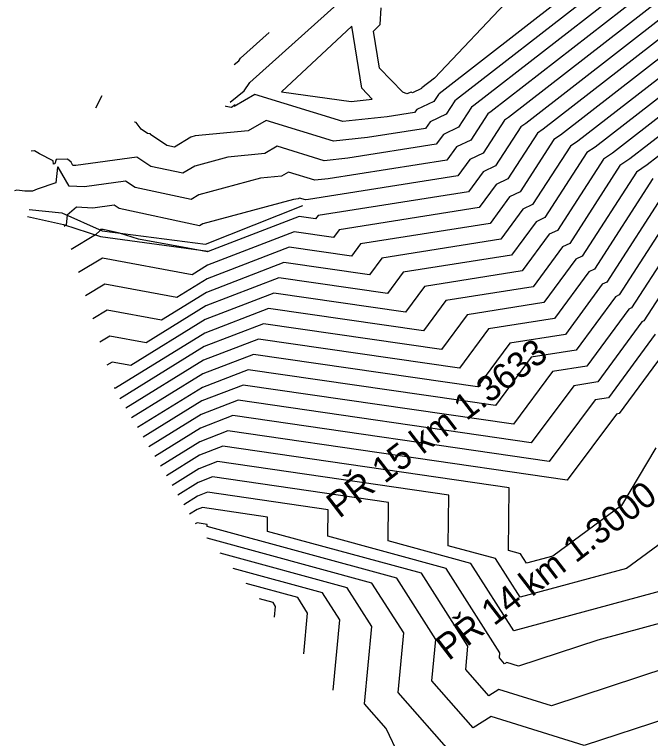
# Model space of a CAD drawing. Extents: x -549238 to -546764, y -1036895 to -1033794.
# Drawn here: x -549025.3 to -548800.9, y -1034580.6 to -1034325.1 of the extents above; entities that cross this region are included whole.
import ezdxf

# ---------------------------------------------------------------- set-up
doc = ezdxf.new("R2010")
doc.units = 0
for name, color, linetype in [('hlavni_vrst', 7, 'Continuous'), ('hrana_L', 7, 'Continuous'), ('norm_vrst', 7, 'Continuous'), ('x_popis_pricne_rezy_C12', 7, 'Continuous')]:
    doc.layers.add(name, color=color, linetype=linetype)

msp = doc.modelspace()

# ---------------------------------------------------------------- linework, layer by layer
at = {"layer": 'hlavni_vrst'}
for p, q in [((-548827.23, -1034315.61), (-548875.4, -1034353.08)), ((-548942.26, -1034349.1), (-548911.49, -1034321.45)), ((-548791.42, -1034322), (-548844.83, -1034363.54)), ((-548906.26, -1034329.26), (-548931.06, -1034352.35)), ((-548902.78, -1034351.17), (-548906.26, -1034329.26)), ((-548780.95, -1034348.1), (-548814.25, -1034374.01)), ((-548944.23, -1034352.06), (-548942.26, -1034349.1)), ((-548899.05, -1034354.99), (-548902.78, -1034351.17)), ((-548949.17, -1034356.03), (-548944.23, -1034352.06)), ((-548940.52, -1034353.34), (-548947.76, -1034357.55)), ((-548909.51, -1034362.87), (-548940.52, -1034353.34)), ((-548931.06, -1034352.35), (-548906.47, -1034355.85)), ((-548875.73, -1034353.29), (-548877.34, -1034355.79)), ((-548875.4, -1034353.08), (-548875.73, -1034353.29)), ((-548906.47, -1034355.85), (-548899.05, -1034354.99)), ((-548877.34, -1034355.79), (-548883.32, -1034358.63)), ((-548950.73, -1034357.6), (-548950.77, -1034357.3)), ((-548948.77, -1034357.93), (-548950.73, -1034357.6)), ((-548947.43, -1034357.02), (-548948.77, -1034357.93)), ((-548947.76, -1034357.55), (-548947.43, -1034357.02)), ((-548883.32, -1034358.63), (-548884.11, -1034359.7)), ((-548893.78, -1034361.24), (-548909.51, -1034362.87)), ((-548884.11, -1034359.7), (-548893.78, -1034361.24)), ((-548844.83, -1034363.54), (-548846.62, -1034364.71)), ((-548846.62, -1034364.71), (-548855.54, -1034378.56)), ((-548814.25, -1034374.01), (-548817.51, -1034376.13)), ((-548817.51, -1034376.13), (-548833.75, -1034401.33)), ((-548855.54, -1034378.56), (-548859.96, -1034380.65)), ((-548859.96, -1034380.65), (-548865.11, -1034387.66)), ((-548865.11, -1034387.66), (-548918.22, -1034396.08)), ((-548788.4, -1034387.55), (-548811.96, -1034424.09)), ((-548924.84, -1034396.37), (-548956.96, -1034408.78)), ((-548919.06, -1034397.21), (-548924.84, -1034396.37)), ((-548918.22, -1034396.08), (-548919.06, -1034397.21)), ((-548995.14, -1034401.33), (-548996.72, -1034402.87)), ((-548995.12, -1034401.14), (-548995.14, -1034401.33)), ((-548994.93, -1034400.98), (-548995.12, -1034401.14)), ((-548994.6, -1034401), (-548994.93, -1034400.98)), ((-548994.18, -1034400.94), (-548994.6, -1034401)), ((-548994.08, -1034401.01), (-548994.18, -1034400.94)), ((-548988.34, -1034402.23), (-548994.08, -1034401.01)), ((-548981.56, -1034404.41), (-548988.34, -1034402.23)), ((-548833.75, -1034401.33), (-548836.59, -1034402.68)), ((-548996.72, -1034402.87), (-549005.29, -1034408.04)), ((-548964.19, -1034407.61), (-548981.56, -1034404.41)), ((-548836.59, -1034402.68), (-548846.11, -1034415.62)), ((-548957.17, -1034408.91), (-548964.19, -1034407.61)), ((-548956.96, -1034408.78), (-548957.17, -1034408.91)), ((-548846.11, -1034415.62), (-548880.61, -1034421.09)), ((-548880.61, -1034421.09), (-548887.34, -1034430.14)), ((-548933.84, -1034423.41), (-548958, -1034432.75)), ((-548887.34, -1034430.14), (-548933.84, -1034423.41)), ((-548813.23, -1034424.7), (-548827.11, -1034443.57)), ((-548811.96, -1034424.09), (-548813.23, -1034424.7)), ((-548958, -1034432.75), (-548984.28, -1034449)), ((-548827.11, -1034443.57), (-548843, -1034446.09)), ((-548990.91, -1034447.77), (-548992.7, -1034448.85)), ((-548984.28, -1034449), (-548990.91, -1034447.77)), ((-548843, -1034446.09), (-548855.62, -1034463.08)), ((-548942.84, -1034450.45), (-548959.04, -1034456.71)), ((-548855.62, -1034463.08), (-548942.84, -1034450.45)), ((-548959.04, -1034456.71), (-548981.97, -1034470.89)), ((-548951.84, -1034477.49), (-548960.08, -1034480.67)), ((-548850.73, -1034492.13), (-548951.84, -1034477.49)), ((-548798.95, -1034478.01), (-548811.07, -1034498.41)), ((-548960.08, -1034480.67), (-548971.75, -1034487.89)), ((-548850.95, -1034514.29), (-548850.73, -1034492.13)), ((-548811.07, -1034498.41), (-548835.34, -1034516.27)), ((-548961.12, -1034504.64), (-548961.53, -1034504.89)), ((-548960.84, -1034504.53), (-548961.12, -1034504.64)), ((-548957.32, -1034505.04), (-548960.84, -1034504.53)), ((-548957.33, -1034505.81), (-548957.32, -1034505.04)), ((-548890.45, -1034524.01), (-548957.33, -1034505.81)), ((-548846.81, -1034515.42), (-548850.95, -1034514.29)), ((-548844.67, -1034518.77), (-548846.81, -1034515.42)), ((-548835.34, -1034516.27), (-548844.67, -1034518.77)), ((-548876.65, -1034545.68), (-548890.45, -1034524.01)), ((-548934.1, -1034532.6), (-548938.9, -1034531.29)), ((-548938.9, -1034531.29), (-548938.9, -1034531.29)), ((-548933.17, -1034534.06), (-548934.1, -1034532.6)), ((-548933.52, -1034537.84), (-548933.17, -1034534.06)), ((-548877.99, -1034560.29), (-548876.65, -1034545.68)), ((-548863.43, -1034576.88), (-548877.99, -1034560.29)), ((-548752.79, -1034559.55), (-548824.26, -1034583.07)), ((-548857.14, -1034572.85), (-548863.43, -1034576.88)), ((-548824.26, -1034583.07), (-548857.14, -1034572.85))]:
    msp.add_line(p, q, dxfattribs=at)
at = {"layer": 'hrana_L'}
for p, q in [((-549020.11, -1034393.96), (-549008.6, -1034395.1)), ((-548957.94, -1034406.11), (-548923.56, -1034392.53)), ((-549020.77, -1034396.39), (-549008.01, -1034399.22)), ((-549008.6, -1034395.1), (-548994.42, -1034401.45)), ((-549008.01, -1034399.22), (-548994.94, -1034403.44)), ((-548994.42, -1034401.45), (-548957.94, -1034406.11)), ((-548994.94, -1034403.44), (-548956.95, -1034408.59))]:
    msp.add_line(p, q, dxfattribs=at)
at = {"layer": 'norm_vrst'}
for p, q in [((-548832.35, -1034300.26), (-548877.14, -1034347.58)), ((-548799.8, -1034301.11), (-548869.29, -1034355.17)), ((-548797.7, -1034306.33), (-548863.17, -1034357.27)), ((-548795.61, -1034311.56), (-548857.06, -1034359.36)), ((-548793.52, -1034316.78), (-548850.94, -1034361.45)), ((-548896.31, -1034328.69), (-548895.92, -1034322.78)), ((-548789.33, -1034327.22), (-548838.71, -1034365.64)), ((-548898.6, -1034331.03), (-548896.31, -1034328.69)), ((-548945.53, -1034340.53), (-548935.41, -1034331.44)), ((-548896.52, -1034344.11), (-548898.6, -1034331.03)), ((-548787.23, -1034332.44), (-548832.6, -1034367.73)), ((-548785.14, -1034337.66), (-548826.48, -1034369.82)), ((-548946.18, -1034341.51), (-548945.53, -1034340.53)), ((-548947.8, -1034342.82), (-548946.18, -1034341.51)), ((-548783.05, -1034342.88), (-548820.37, -1034371.91)), ((-548888.3, -1034352.54), (-548896.52, -1034344.11)), ((-548877.14, -1034347.58), (-548881.52, -1034350.99)), ((-548881.55, -1034351.01), (-548881.69, -1034351.24)), ((-548881.52, -1034350.99), (-548881.55, -1034351.01)), ((-548996.66, -1034358.1), (-548994.4, -1034353.67)), ((-548886.88, -1034353.16), (-548888.3, -1034352.54)), ((-548885.35, -1034352.57), (-548886.88, -1034353.16)), ((-548884.83, -1034352.73), (-548885.35, -1034352.57)), ((-548881.69, -1034351.24), (-548884.83, -1034352.73)), ((-548778.86, -1034353.32), (-548808.14, -1034376.1)), ((-548869.9, -1034355.58), (-548872.98, -1034360.34)), ((-548869.29, -1034355.17), (-548869.9, -1034355.58)), ((-548864.08, -1034357.86), (-548868.62, -1034364.9)), ((-548863.17, -1034357.27), (-548864.08, -1034357.86)), ((-548776.77, -1034358.54), (-548802.02, -1034378.19)), ((-548872.98, -1034360.34), (-548878.65, -1034363.04)), ((-548858.26, -1034360.14), (-548864.26, -1034369.45)), ((-548857.06, -1034359.36), (-548858.26, -1034360.14)), ((-548982.93, -1034363.12), (-548982.82, -1034362.98)), ((-548982.38, -1034363.25), (-548982.93, -1034363.12)), ((-548980.67, -1034365.6), (-548982.38, -1034363.25)), ((-548936.57, -1034362.48), (-548942.86, -1034366.13)), ((-548912.78, -1034369.79), (-548936.57, -1034362.48)), ((-548878.65, -1034363.04), (-548880.31, -1034365.29)), ((-548852.44, -1034362.43), (-548859.9, -1034374)), ((-548850.94, -1034361.45), (-548852.44, -1034362.43)), ((-548980.67, -1034365.6), (-548980.68, -1034365.62)), ((-548978.45, -1034367.12), (-548980.68, -1034365.62)), ((-548942.86, -1034366.13), (-548961.6, -1034367.99)), ((-548880.31, -1034365.29), (-548900.72, -1034368.53)), ((-548868.62, -1034364.9), (-548873.98, -1034367.44)), ((-548838.71, -1034365.64), (-548840.79, -1034366.99)), ((-548977.35, -1034367.27), (-548978.45, -1034367.12)), ((-548977.38, -1034367.51), (-548977.35, -1034367.27)), ((-548971.54, -1034371.36), (-548977.38, -1034367.51)), ((-548963.12, -1034368.4), (-548968.87, -1034371.92)), ((-548961.6, -1034367.99), (-548963.12, -1034368.4)), ((-548900.72, -1034368.53), (-548912.78, -1034369.79)), ((-548873.98, -1034367.44), (-548876.51, -1034370.89)), ((-548840.79, -1034366.99), (-548851.18, -1034383.11)), ((-548832.6, -1034367.73), (-548834.97, -1034369.28)), ((-548968.87, -1034371.92), (-548971.54, -1034371.36)), ((-548932.61, -1034371.61), (-548936.99, -1034374.16)), ((-548916.06, -1034376.7), (-548932.61, -1034371.61)), ((-548876.51, -1034370.89), (-548907.66, -1034375.82)), ((-548864.26, -1034369.45), (-548869.31, -1034371.85)), ((-548834.97, -1034369.28), (-548846.83, -1034387.66)), ((-548829.15, -1034371.56), (-548842.47, -1034392.22)), ((-548826.48, -1034369.82), (-548829.15, -1034371.56)), ((-549018.28, -1034373.28), (-549019.42, -1034373.36)), ((-549016.49, -1034374.33), (-549018.28, -1034373.28)), ((-548936.99, -1034374.16), (-548950.03, -1034375.45)), ((-548869.31, -1034371.85), (-548872.71, -1034376.48)), ((-548859.9, -1034374), (-548864.63, -1034376.25)), ((-548823.33, -1034373.85), (-548838.11, -1034396.77)), ((-548820.37, -1034371.91), (-548823.33, -1034373.85)), ((-549011.66, -1034376.73), (-549016.49, -1034374.33)), ((-549011.62, -1034377.93), (-549011.66, -1034376.73)), ((-549010.65, -1034376.26), (-549011.07, -1034377.78)), ((-549006.64, -1034376.21), (-549010.65, -1034376.26)), ((-549005.38, -1034377.17), (-549006.64, -1034376.21)), ((-548982.2, -1034375.46), (-549003.72, -1034378.43)), ((-548977.17, -1034378.77), (-548982.2, -1034375.46)), ((-548950.03, -1034375.45), (-548961.72, -1034378.59)), ((-548907.66, -1034375.82), (-548916.06, -1034376.7)), ((-548872.71, -1034376.48), (-548914.6, -1034383.12)), ((-548864.63, -1034376.25), (-548868.91, -1034382.07)), ((-548808.14, -1034376.1), (-548811.68, -1034378.41)), ((-549011.07, -1034377.78), (-549011.62, -1034377.93)), ((-549010.13, -1034379.01), (-549010.74, -1034384.56)), ((-549010, -1034378.98), (-549010.13, -1034379.01)), ((-549009.99, -1034378.95), (-549010, -1034378.98)), ((-549009.91, -1034378.95), (-549009.99, -1034378.95)), ((-549009.89, -1034378.96), (-549009.91, -1034378.95)), ((-549006.09, -1034385.65), (-549009.89, -1034378.96)), ((-549004.7, -1034378.38), (-549005.38, -1034377.17)), ((-549003.72, -1034378.43), (-549004.7, -1034378.38)), ((-548965.92, -1034381.16), (-548977.17, -1034378.77)), ((-548961.72, -1034378.59), (-548965.92, -1034381.16)), ((-548811.68, -1034378.41), (-548829.39, -1034405.88)), ((-548802.02, -1034378.19), (-548805.86, -1034380.7)), ((-548928.66, -1034380.75), (-548931.13, -1034382.18)), ((-548919.34, -1034383.61), (-548928.66, -1034380.75)), ((-548805.86, -1034380.7), (-548825.03, -1034410.43)), ((-548986.19, -1034383.96), (-549000.68, -1034385.96)), ((-548982.81, -1034386.18), (-548986.19, -1034383.96)), ((-548938.47, -1034382.91), (-548960.32, -1034388.78)), ((-548931.13, -1034382.18), (-548938.47, -1034382.91)), ((-548868.91, -1034382.07), (-548921.55, -1034390.41)), ((-548914.6, -1034383.12), (-548919.34, -1034383.61)), ((-548851.18, -1034383.11), (-548855.29, -1034385.06)), ((-548800.04, -1034382.98), (-548820.68, -1034414.99)), ((-549017.31, -1034386.75), (-549019.03, -1034387.44)), ((-549010.74, -1034384.56), (-549017.31, -1034386.75)), ((-549000.68, -1034385.96), (-549006.09, -1034385.65)), ((-548962.96, -1034390.4), (-548982.81, -1034386.18)), ((-548855.29, -1034385.06), (-548861.31, -1034393.25)), ((-548794.22, -1034385.26), (-548816.32, -1034419.54)), ((-549024.47, -1034387.15), (-549025.35, -1034387.37)), ((-549021.64, -1034387.45), (-549024.47, -1034387.15)), ((-549019.03, -1034387.44), (-549021.64, -1034387.45)), ((-548960.32, -1034388.78), (-548962.96, -1034390.4)), ((-548850.61, -1034389.46), (-548857.51, -1034398.84)), ((-548846.83, -1034387.66), (-548850.61, -1034389.46)), ((-548926.91, -1034390.37), (-548958.92, -1034398.98)), ((-548925.26, -1034390.2), (-548926.91, -1034390.37)), ((-548924.71, -1034389.88), (-548925.26, -1034390.2)), ((-548922.61, -1034390.53), (-548924.71, -1034389.88)), ((-548921.55, -1034390.41), (-548922.61, -1034390.53)), ((-548782.57, -1034389.83), (-548807.6, -1034428.65)), ((-549003.5, -1034393.14), (-549006.74, -1034395.93)), ((-548997.64, -1034393.48), (-549003.5, -1034393.14)), ((-548990.19, -1034392.45), (-548997.64, -1034393.48)), ((-548988.45, -1034393.59), (-548990.19, -1034392.45)), ((-548960.01, -1034399.64), (-548988.45, -1034393.59)), ((-548861.31, -1034393.25), (-548910.7, -1034401.08)), ((-548845.94, -1034393.87), (-548853.71, -1034404.43)), ((-548842.47, -1034392.22), (-548845.94, -1034393.87)), ((-548776.75, -1034392.12), (-548803.24, -1034433.2)), ((-549006.74, -1034395.93), (-549007.06, -1034399.38)), ((-548838.11, -1034396.77), (-548841.27, -1034398.27)), ((-549007.17, -1034399.49), (-549007.81, -1034399.87)), ((-549007.06, -1034399.38), (-549007.17, -1034399.49)), ((-548958.92, -1034398.98), (-548960.01, -1034399.64)), ((-548857.51, -1034398.84), (-548903.18, -1034406.08)), ((-548841.27, -1034398.27), (-548849.91, -1034410.03)), ((-548926.64, -1034401.78), (-548957.17, -1034413.57)), ((-548912.71, -1034403.79), (-548926.64, -1034401.78)), ((-548910.7, -1034401.08), (-548912.71, -1034403.79)), ((-548853.71, -1034404.43), (-548895.65, -1034411.08)), ((-548928.44, -1034407.19), (-548957.37, -1034418.37)), ((-548906.37, -1034410.38), (-548928.44, -1034407.19)), ((-548903.18, -1034406.08), (-548906.37, -1034410.38)), ((-548831.92, -1034407.08), (-548842.31, -1034421.21)), ((-548829.39, -1034405.88), (-548831.92, -1034407.08)), ((-548994.25, -1034411.06), (-549002.77, -1034416.2)), ((-548962.59, -1034416.93), (-548994.25, -1034411.06)), ((-548895.65, -1034411.08), (-548900.02, -1034416.97)), ((-548849.91, -1034410.03), (-548888.13, -1034416.09)), ((-548827.25, -1034411.48), (-548838.51, -1034426.8)), ((-548825.03, -1034410.43), (-548827.25, -1034411.48)), ((-548957.17, -1034413.57), (-548962.59, -1034416.93)), ((-548930.24, -1034412.59), (-548957.58, -1034423.16)), ((-548900.02, -1034416.97), (-548930.24, -1034412.59)), ((-548820.68, -1034414.99), (-548822.58, -1034415.89)), ((-548888.13, -1034416.09), (-548893.68, -1034423.56)), ((-548822.58, -1034415.89), (-548834.71, -1034432.39)), ((-548957.37, -1034418.37), (-548968.01, -1034424.95)), ((-548932.04, -1034418), (-548957.79, -1034427.95)), ((-548893.68, -1034423.56), (-548932.04, -1034418)), ((-548816.32, -1034419.54), (-548817.9, -1034420.29)), ((-548993.41, -1034420.24), (-549000.25, -1034424.36)), ((-548968.01, -1034424.95), (-548993.41, -1034420.24)), ((-548842.31, -1034421.21), (-548873.09, -1034426.09)), ((-548817.9, -1034420.29), (-548830.91, -1034437.98)), ((-548957.58, -1034423.16), (-548973.44, -1034432.96)), ((-548873.09, -1034426.09), (-548880.99, -1034436.73)), ((-548838.51, -1034426.8), (-548865.57, -1034431.09)), ((-548992.58, -1034429.41), (-548997.74, -1034432.52)), ((-548973.44, -1034432.96), (-548992.58, -1034429.41)), ((-548957.79, -1034427.95), (-548978.86, -1034440.98)), ((-548935.64, -1034428.82), (-548958.21, -1034437.54)), ((-548880.99, -1034436.73), (-548935.64, -1034428.82)), ((-548808.56, -1034429.1), (-548823.31, -1034449.17)), ((-548807.6, -1034428.65), (-548808.56, -1034429.1)), ((-548865.57, -1034431.09), (-548874.65, -1034443.32)), ((-548834.71, -1034432.39), (-548858.04, -1034436.09)), ((-548937.44, -1034434.22), (-548958.42, -1034442.33)), ((-548874.65, -1034443.32), (-548937.44, -1034434.22)), ((-548803.88, -1034433.51), (-548819.51, -1034454.76)), ((-548803.24, -1034433.2), (-548803.88, -1034433.51)), ((-548958.21, -1034437.54), (-548989.7, -1034457.02)), ((-548858.04, -1034436.09), (-548868.3, -1034449.91)), ((-548830.91, -1034437.98), (-548850.52, -1034441.09)), ((-548799.21, -1034437.91), (-548815.71, -1034460.35)), ((-548991.75, -1034438.59), (-548995.22, -1034440.69)), ((-548978.86, -1034440.98), (-548991.75, -1034438.59)), ((-548939.24, -1034439.63), (-548958.62, -1034447.12)), ((-548868.3, -1034449.91), (-548939.24, -1034439.63)), ((-548958.42, -1034442.33), (-548988.11, -1034460.7)), ((-548850.52, -1034441.09), (-548861.96, -1034456.49)), ((-548794.54, -1034442.31), (-548811.91, -1034465.94)), ((-548941.04, -1034445.04), (-548958.83, -1034451.92)), ((-548861.96, -1034456.49), (-548941.04, -1034445.04)), ((-548958.62, -1034447.12), (-548986.06, -1034464.09)), ((-548823.31, -1034449.17), (-548835.48, -1034451.1)), ((-548958.83, -1034451.92), (-548984.02, -1034467.49)), ((-548835.48, -1034451.1), (-548849.27, -1034469.67)), ((-548944.64, -1034455.86), (-548959.25, -1034461.5)), ((-548849.27, -1034469.67), (-548944.64, -1034455.86)), ((-548819.51, -1034454.76), (-548827.96, -1034456.1)), ((-548990.08, -1034456.95), (-548990.18, -1034457.01)), ((-548989.7, -1034457.02), (-548990.08, -1034456.95)), ((-548827.96, -1034456.1), (-548842.93, -1034476.26)), ((-548815.71, -1034460.35), (-548820.43, -1034461.1)), ((-548959.25, -1034461.5), (-548979.93, -1034474.29)), ((-548946.44, -1034461.26), (-548959.46, -1034466.3)), ((-548842.93, -1034476.26), (-548946.44, -1034461.26)), ((-548820.43, -1034461.1), (-548836.58, -1034482.84)), ((-548812.91, -1034466.1), (-548830.24, -1034489.43)), ((-548811.91, -1034465.94), (-548812.91, -1034466.1)), ((-548959.46, -1034466.3), (-548977.88, -1034477.69)), ((-548948.24, -1034466.67), (-548959.67, -1034471.09)), ((-548836.58, -1034482.84), (-548948.24, -1034466.67)), ((-548959.67, -1034471.09), (-548975.84, -1034481.09)), ((-548950.04, -1034472.08), (-548959.87, -1034475.88)), ((-548830.24, -1034489.43), (-548950.04, -1034472.08)), ((-548959.87, -1034475.88), (-548973.8, -1034484.49)), ((-548953.64, -1034482.9), (-548960.29, -1034485.47)), ((-548872.05, -1034494.71), (-548953.64, -1034482.9)), ((-548960.29, -1034485.47), (-548969.71, -1034491.29)), ((-548955.44, -1034488.3), (-548960.5, -1034490.26)), ((-548893.37, -1034497.29), (-548955.44, -1034488.3)), ((-548960.5, -1034490.26), (-548967.66, -1034494.69)), ((-548957.24, -1034493.71), (-548960.71, -1034495.05)), ((-548914.69, -1034499.87), (-548957.24, -1034493.71)), ((-548960.71, -1034495.05), (-548965.62, -1034498.09)), ((-548872.23, -1034512.59), (-548872.05, -1034494.71)), ((-548959.04, -1034499.12), (-548960.91, -1034499.84)), ((-548936, -1034502.46), (-548959.04, -1034499.12)), ((-548893.5, -1034510.9), (-548893.37, -1034497.29)), ((-548960.91, -1034499.84), (-548963.57, -1034501.49)), ((-548914.78, -1034509.2), (-548914.69, -1034499.87)), ((-548936.05, -1034507.5), (-548936, -1034502.46)), ((-548881.73, -1034522.29), (-548936.05, -1034507.5)), ((-548873, -1034520.57), (-548914.78, -1034509.2)), ((-548791.5, -1034507.46), (-548809.32, -1034520.57)), ((-548957.37, -1034509.89), (-548957.4, -1034509.89)), ((-548899.18, -1034525.73), (-548957.37, -1034509.89)), ((-548864.27, -1034518.85), (-548893.5, -1034510.9)), ((-548855.54, -1034517.14), (-548872.23, -1034512.59)), ((-548952.76, -1034515.24), (-548952.77, -1034515.24)), ((-548907.91, -1034527.45), (-548952.76, -1034515.24)), ((-548846.92, -1034530.67), (-548855.54, -1034517.14)), ((-548849.16, -1034542.56), (-548864.27, -1034518.85)), ((-548948.14, -1034520.59), (-548948.15, -1034520.59)), ((-548916.64, -1034529.16), (-548948.14, -1034520.59)), ((-548865.34, -1034548), (-548881.73, -1034522.29)), ((-548854.04, -1034550.33), (-548873, -1034520.57)), ((-548809.32, -1034520.57), (-548846.92, -1034530.67)), ((-548783.3, -1034524.87), (-548849.16, -1034542.56)), ((-548943.52, -1034525.94), (-548943.53, -1034525.94)), ((-548925.37, -1034530.88), (-548943.52, -1034525.94)), ((-548899.26, -1034541.03), (-548907.91, -1034527.45)), ((-548887.95, -1034543.35), (-548899.18, -1034525.73)), ((-548910.56, -1034538.71), (-548916.64, -1034529.16)), ((-548757.28, -1034529.16), (-548819.48, -1034545.87)), ((-548921.87, -1034536.38), (-548925.37, -1034530.88)), ((-548923.18, -1034550.67), (-548921.87, -1034536.38)), ((-548740.46, -1034537.68), (-548835.83, -1034569.07)), ((-548912.84, -1034563.5), (-548910.56, -1034538.71)), ((-548901.77, -1034568.39), (-548899.26, -1034541.03)), ((-548889.88, -1034564.34), (-548887.95, -1034543.35)), ((-548819.48, -1034545.87), (-548847.4, -1034555.06)), ((-548866.1, -1034556.23), (-548865.34, -1034548)), ((-548854.21, -1034552.18), (-548854.04, -1034550.33)), ((-548852.36, -1034554.28), (-548854.21, -1034552.18)), ((-548851.57, -1034553.77), (-548852.36, -1034554.28)), ((-548847.4, -1034555.06), (-548851.57, -1034553.77)), ((-548857.9, -1034565.58), (-548866.1, -1034556.23)), ((-548868.96, -1034588.18), (-548889.88, -1034564.34)), ((-548854.35, -1034563.31), (-548857.9, -1034565.58)), ((-548835.83, -1034569.07), (-548854.35, -1034563.31)), ((-548894.14, -1034577.09), (-548901.77, -1034568.39)), ((-548882.73, -1034600.74), (-548894.14, -1034577.09))]:
    msp.add_line(p, q, dxfattribs=at)

# ---------------------------------------------------------------- texts
at = {"layer": 'x_popis_pricne_rezy_C12'}
for s, p in [('PŘ 15 km 1.3633', (-548910.72, -1034503.16)), ('PŘ 14 km 1.3000', (-548872.13, -1034553.38)), ('PŘ 13 km 1.2000', (-548811.2, -1034632.67))]:
    msp.add_text(s, height=9.0627, rotation=37.5364, dxfattribs=at).set_placement(p)

doc.saveas('drawing.dxf')
